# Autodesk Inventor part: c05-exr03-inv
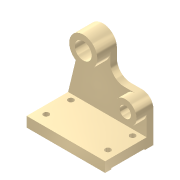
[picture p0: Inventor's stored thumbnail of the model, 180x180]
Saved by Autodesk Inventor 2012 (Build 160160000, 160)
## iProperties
Shininess: 64.0
Length Units: 11269
Angle Units: 11279
Time Units: 11290
Mass Units: 11283
Length Display Precision: 3
Angle Display Precision: 2
Compacted: True
Part Number: c05-exr03-inv
Document SubType Name: Modeling
Created: 2003-10
Designer: Owner
Manufacturer: Standard
Standards Organization: Custom
Density: 1 g/cm^3
Material: Default
Density: 0.0
Volumn: 0.0
Area: 0.0
PropertySet Name: Model Information
Control State: 0
Master: False
Checked Out: False
Author: Owner
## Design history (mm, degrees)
sketch "Sketch1"
  geometry: L1 (28, -7)-(28, -9); L2 (-32, -7)-(28, -7); L3 (-32, -9)-(-32, -7); L4 (-43, -9)-(-32, -9); L5 (-43, 9)-(-43, -9); L6 (43, 9)-(-43, 9); L7 (43, -9)-(43, 9); L8 (28, -9)-(43, -9)
  constraints: 16 end point, 4 horizontal, 4 vertical, 1 collinear, 1 other
  dimensions: "d1" = 18 distance of L5.start L4.start; "d3" = 2 distance of L1.start L1.end; "d5" = 86 distance of L6.start L5.start; "d7" = 15 distance of L1.end L7.start; "d9" = 60 distance of L2.start L1.start
extrude "ExtrusionMidplane1" new body sketch "Sketch1" stored distance "d10" = 140; taper "d11" = 0 deg
sketch "Sketch2"
  geometry: L1 (140, -18)-(0, -18); L2 (25.706, -123.897)-(0, -18); L3 (75, -101)-(75, -118); L4 (120, -76)-(100, -76); L5 (140, -18)-(140, -56); L6 (0, -18)-(140, -18) reference; L7 (140, -18)-(140, 0) reference; A1 r 25 centre (50, -118) between (25.706, -123.897) and (75, -118); A2 r 25 centre (100, -101) between (100, -76) and (75, -101); A3 r 20 centre (120, -56) between (120, -76) and (140, -56); 1 further point
  constraints: 10 end point, 6 point on circle, 6 tangent, 3 centre point, 2 collinear, 2 horizontal, 2 vertical
  dimensions: "d16" = 20 radius of A3; "d18" = 25 radius of A2; "d20" = 25 radius of A1; "d22" = 118 vertical distance of A1.centre point (0, 0); "d24" = 56 vertical distance of A3.centre L7.end; "d27" = 50 horizontal distance of A1.centre L6.start
extrude "ExtrusionBlind1" join sketch "Sketch2" distance "d28" = 12; taper "d29" = 0 deg
sketch "Sketch3"
  geometry: C1 r 25 at (50, 118); C2 r 25 at (50, 118)
  constraints: 2 centre point, 1 coincident
  dimensions: "d33" = 50 diameter of C1
extrude "ExtrusionBlind2" join sketch "Sketch3" distance "d34" = 23; taper "d35" = 0 deg
sketch "Sketch4"
  geometry: C1 r 20 at (120, 56); C2 r 20 at (120, 56)
  constraints: 2 centre point, 1 coincident
extrude "ExtrusionBlind3" join sketch "Sketch4" distance "d36" = 18; taper "d37" = 0 deg
sketch "Sketch5"
  geometry: L1 (0, -12)-(0, -86) reference; L2 (0, -86)-(140, -86) reference; 1 further point
  dimensions: "d39" = 15 distance from line of L1 point (15, -66); "d41" = 20 distance from line of L2 point (15, -66)
hole "Hole1" sketch "Sketch5" at (15, -66) diameter "d42" = 10; stored, may be unused: countersink angle "d46" = 82 deg, drill point angle "d48" = 118 deg; dims "d43" = 6, "d44" = 4, "d45" = 2, "d47" = 8
sketch "Sketch6"
  geometry: C1 r 25 at (0, 0) reference; 1 further point
hole "Hole2" sketch "Sketch6" at (0, 0) diameter "d51" = 30; stored, may be unused: countersink angle "d55" = 82 deg, drill point angle "d57" = 118 deg; dims "d52" = 6, "d53" = 4, "d54" = 2, "d56" = 8
sketch "Sketch7"
  geometry: C1 r 20 at (0, 0) reference; 1 further point
hole "Hole3" sketch "Sketch7" at (0, 0) diameter "d58" = 20; stored, may be unused: countersink angle "d62" = 82 deg, drill point angle "d64" = 118 deg; dims "d59" = 6, "d60" = 4, "d61" = 2, "d63" = 8
workaxis "Work Axis1"
workaxis "Work Axis2"
pattern_linear "RectangularPattern1" dims "d67" = 110, "d70" = 44
body "Solid1"
other parameters: "d0" = 18 (derived), "d2" = 2 (derived), "d4" = 86 (derived), "d6" = 15 (derived), "d12" = 0, "d13" = 0, "d14" = 0, "d17" = 25 (derived), "d19" = 25 (derived), "d21" = 118 (derived), "d23" = 56 (derived), "d25" = 0 (derived), "d30" = 0, "d31" = 0, "d38" = 15 (derived), "d49" = 0, "d50" = 0
